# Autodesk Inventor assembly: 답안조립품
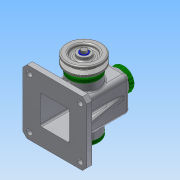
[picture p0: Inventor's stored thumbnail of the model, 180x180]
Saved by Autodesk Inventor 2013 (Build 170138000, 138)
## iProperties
Created: 2018-10
Part Number: 답안조립품
Document SubType Name: Assembly
Designer: Administrator
Author: Administrator
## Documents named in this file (14)
- C:\Users\Administrator\Desktop\481013V1009\답안조립품.iam
- C:\Users\Administrator\Desktop\481013V1009\본체.ipt
- C:\Users\Administrator\Desktop\481013V1009\V-벨트풀리.ipt
- C:\Users\Administrator\Desktop\481013V1009\뒤커버.ipt
- C:\Users\Administrator\Desktop\481013V1009\멈춤링 15 x 1.ipt
- C:\Users\Administrator\Desktop\481013V1009\베어링 15 x 35 x 11.ipt
- C:\Users\Administrator\Desktop\481013V1009\볼트 M4 x 10.ipt
- C:\Users\Administrator\Desktop\481013V1009\볼트 M6 x 12.ipt
- C:\Users\Administrator\Desktop\481013V1009\상부캡.ipt
- C:\Users\Administrator\Desktop\481013V1009\앞커버.ipt
- C:\Users\Administrator\Desktop\481013V1009\오일실 15 25 7.ipt
- C:\Users\Administrator\Desktop\481013V1009\와셔.ipt
- C:\Users\Administrator\Desktop\481013V1009\축.ipt
- C:\Users\Administrator\Desktop\481013V1009\키 5 x 5 x 14.ipt
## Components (1 placed, 1 different names)
1. V-벨트풀리:1
